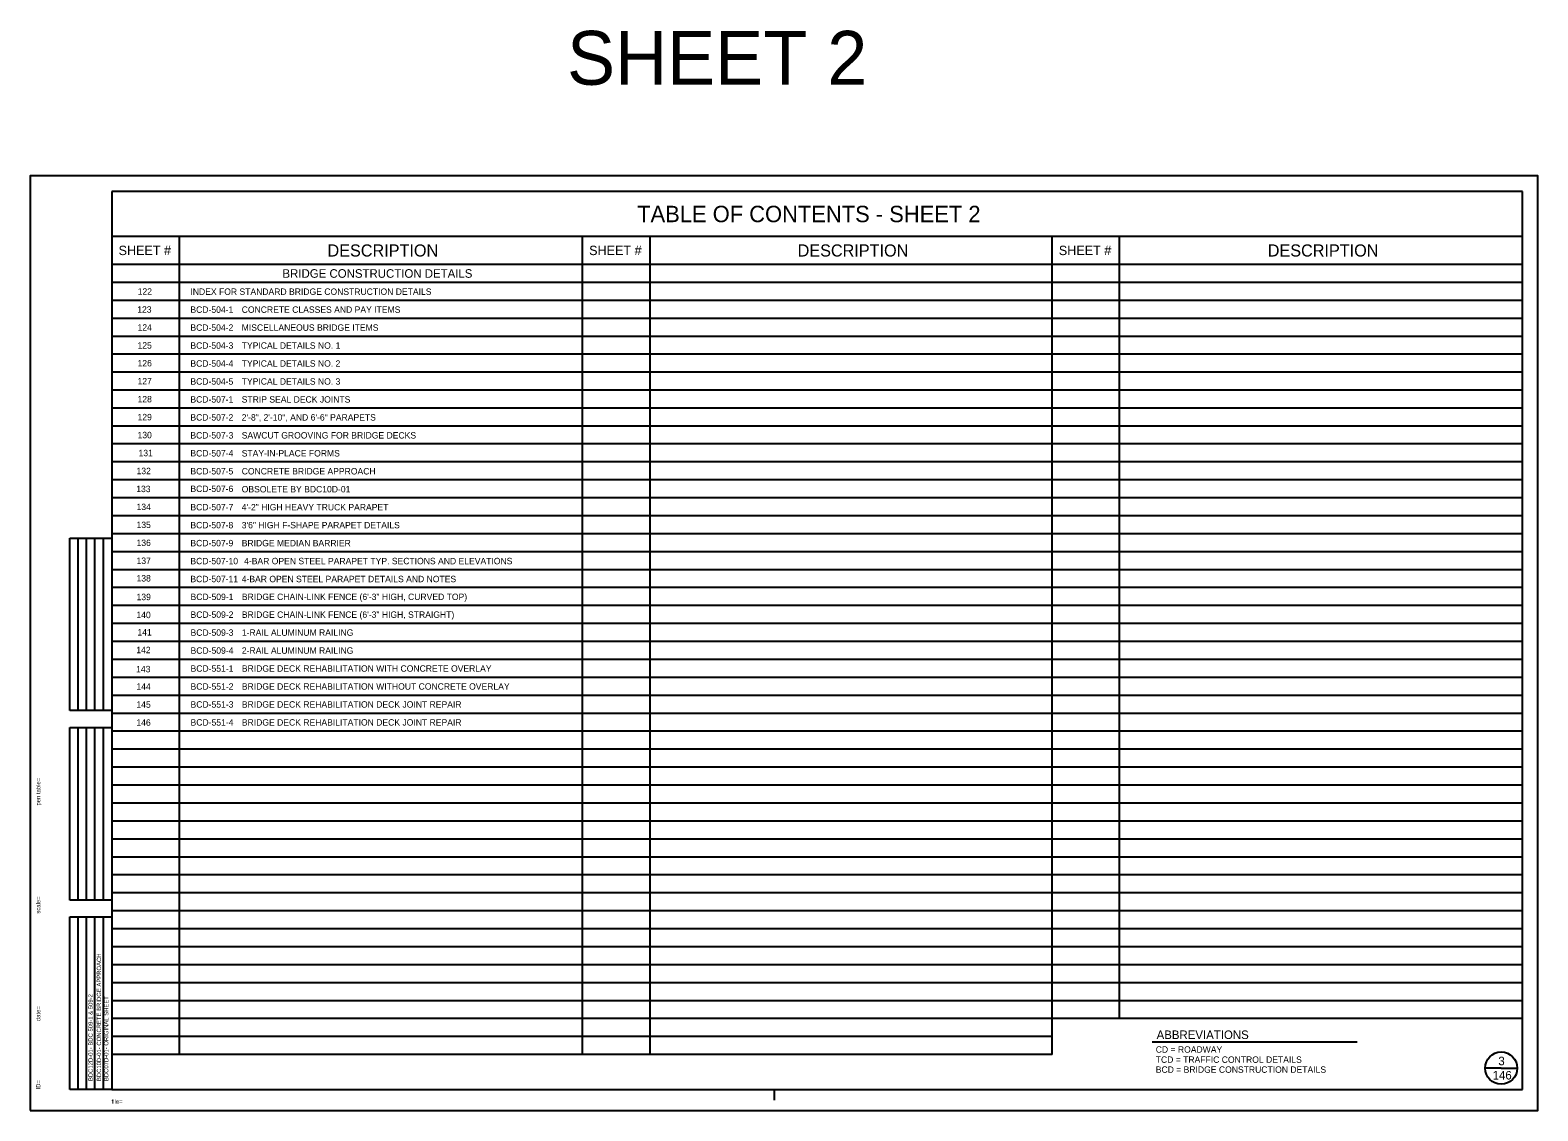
# Model space of a CAD drawing. Extents: x 499943 to 502231, y 501090 to 501849.
# Drawn here: x 501173 to 502231, y 501090 to 501849 of the extents above; entities that cross this region are included whole.
import ezdxf

# ---------------------------------------------------------------- set-up
doc = ezdxf.new("R2010")
doc.units = 0
for name, color, linetype in [('1', 7, 'Continuous'), ('39', 7, 'Continuous'), ('41', 7, 'Continuous')]:
    doc.layers.add(name, color=color, linetype=linetype)

msp = doc.modelspace()

# ---------------------------------------------------------------- linework, layer by layer
at = {"layer": '1'}
for p, q in [((502224.2, 501746.3), (501176, 501746.3)), ((501230.6, 501735.3), (501230.6, 501105.3)), ((502220.6, 501735.3), (501230.6, 501735.3)), ((502220.6, 501105.3), (502220.6, 501735.3)), ((501277.9, 501703.8), (501230.6, 501703.8)), ((501277.9, 501703.8), (501277.9, 501129.8)), ((501560.8, 501703.8), (501277.9, 501703.8)), ((501560.8, 501703.8), (501560.8, 501129.8)), ((501608.1, 501703.8), (501560.8, 501703.8)), ((501608.1, 501703.8), (501608.1, 501129.8)), ((501890.5, 501703.8), (501608.1, 501703.8)), ((501937.7, 501703.8), (501890.5, 501703.8)), ((501890.5, 501155), (501890.5, 501703.8)), ((502220.6, 501703.8), (501937.7, 501703.8)), ((501937.7, 501155), (501937.7, 501703.8)), ((502220.6, 501684.1), (501230.6, 501684.1)), ((502220.6, 501671.5), (501230.6, 501671.5)), ((502220.6, 501658.9), (501230.6, 501658.9)), ((502220.6, 501646.3), (501230.6, 501646.3)), ((502220.6, 501633.7), (501230.6, 501633.7)), ((502220.6, 501621.1), (501230.6, 501621.1)), ((502220.6, 501608.5), (501230.6, 501608.5)), ((502220.6, 501595.9), (501230.6, 501595.9)), ((502220.6, 501583.3), (501230.6, 501583.3)), ((502220.6, 501570.7), (501230.6, 501570.7)), ((502220.6, 501558.2), (501230.6, 501558.2)), ((502220.6, 501545.6), (501230.6, 501545.6)), ((502220.6, 501533), (501230.6, 501533)), ((502220.6, 501520.4), (501230.6, 501520.4)), ((502220.6, 501507.8), (501230.6, 501507.8)), ((501201.1, 501371.1), (501201.1, 501492.1)), ((501201.1, 501492.1), (501230.6, 501492.1)), ((501207, 501371.1), (501207, 501492.1)), ((501212.9, 501371.1), (501212.9, 501492.1)), ((501218.8, 501371.1), (501218.8, 501492.1)), ((501224.7, 501371.1), (501224.7, 501492.1)), ((502220.6, 501495.2), (501230.6, 501495.2)), ((502220.6, 501482.6), (501230.6, 501482.6)), ((502220.6, 501470), (501230.6, 501470)), ((502220.6, 501457.4), (501230.6, 501457.4)), ((502220.6, 501444.8), (501230.6, 501444.8)), ((502220.6, 501432.2), (501230.6, 501432.2)), ((502220.6, 501419.6), (501230.6, 501419.6)), ((502220.6, 501407), (501230.6, 501407)), ((502220.6, 501394.4), (501230.6, 501394.4)), ((502220.6, 501381.8), (501230.6, 501381.8)), ((501230.6, 501371.1), (501201.1, 501371.1)), ((502220.6, 501369.2), (501230.6, 501369.2)), ((501201.1, 501238.2), (501201.1, 501359.3)), ((501201.1, 501359.3), (501230.6, 501359.3)), ((501207, 501238.2), (501207, 501359.3)), ((501212.9, 501238.2), (501212.9, 501359.3)), ((501218.8, 501238.2), (501218.8, 501359.3)), ((501224.7, 501238.2), (501224.7, 501359.3)), ((502220.6, 501356.6), (501230.6, 501356.6)), ((502220.6, 501344), (501230.6, 501344)), ((502220.6, 501331.4), (501230.6, 501331.4)), ((502220.6, 501318.8), (501230.6, 501318.8)), ((502220.6, 501306.2), (501230.6, 501306.2)), ((502220.6, 501293.6), (501230.6, 501293.6)), ((502220.6, 501281), (501230.6, 501281)), ((502220.6, 501268.4), (501230.6, 501268.4)), ((502220.6, 501255.8), (501230.6, 501255.8)), ((501230.6, 501238.2), (501201.1, 501238.2)), ((502220.6, 501243.2), (501230.6, 501243.2)), ((501201.1, 501105.3), (501201.1, 501226.4)), ((501201.1, 501226.4), (501230.6, 501226.4)), ((501207, 501105.3), (501207, 501226.4)), ((501212.9, 501105.3), (501212.9, 501226.4)), ((501218.8, 501105.3), (501218.8, 501226.4)), ((501224.7, 501105.3), (501224.7, 501226.4)), ((502220.6, 501230.6), (501230.6, 501230.6)), ((502220.6, 501218), (501230.6, 501218)), ((502220.6, 501205.4), (501230.6, 501205.4)), ((502220.6, 501192.8), (501230.6, 501192.8)), ((502220.6, 501180.2), (501230.6, 501180.2)), ((502220.6, 501167.6), (501230.6, 501167.6)), ((501890.5, 501155), (501230.6, 501155)), ((502220.6, 501155), (501890.5, 501155)), ((501890.5, 501129.8), (501890.5, 501155)), ((501890.5, 501142.4), (501230.6, 501142.4)), ((501890.5, 501142.4), (501560.8, 501142.4)), ((501560.8, 501129.8), (501230.6, 501129.8)), ((501890.5, 501129.8), (501560.8, 501129.8)), ((502104.6, 501138.5), (501960.6, 501138.5)), ((502205.6, 501120.3), (502194.4, 501120.3)), ((502205.6, 501120.3), (502216.9, 501120.3)), ((501230.6, 501105.3), (501201.1, 501105.3)), ((501230.6, 501105.3), (502220.6, 501105.3)), ((501695.6, 501097.8), (501695.6, 501105.3)), ((502228.2, 501090.3), (501180, 501090.3))]:
    msp.add_line(p, q, dxfattribs=at)
msp.add_circle((502205.6, 501120.3), 11.3, dxfattribs=at)
at = {"layer": '41'}
msp.add_lwpolyline([(501173.3, 501090.6), (502231.3, 501090.6), (502231.3, 501746.3), (501173.3, 501746.3)], close=True, dxfattribs=at)

# ---------------------------------------------------------------- texts
at = {"layer": '1'}
for s, height, p in [('TABLE OF CONTENTS - SHEET 2', 11.5, (501599.3, 501713.8)), ('3', 6, (502203.6, 501122.3)), ('146', 6, (502199.6, 501112.3))]:
    msp.add_text(s, height=height, dxfattribs=at).set_placement(p)
for s, height, rotation, p in [('pen table=', 3, 90, (501180.5, 501304.5)), ('...................pentable..................', 0.0432, 90, (501180.5, 501328.4)), ('scale=', 3, 90, (501180.5, 501228.7)), ('......scale......', 0.0432, 90, (501180.5, 501243.4)), ('BDC10D-01- CONCRETE BRIDGE APPROACH', 3, 90, (501223.1, 501111.2)), ('date=', 3, 90, (501180.5, 501153.3)), ('.......time......', 0.0432, 90, (501180.5, 501166.4)), ('BDC12D-01- BDC 509-1 & 509-2', 3, 90, (501217.2, 501111.2)), ('BDC07D-01- ORIGINAL SHEET', 3, 90, (501228.2, 501111.2)), ('ID=', 3, 90, (501180.5, 501105.3)), ('............who............', 0.0432, 90, (501180.5, 501113.3)), ('file=', 3, 360, (501230.5, 501095.3)), ('...................bob..................', 0.0432, 360, (501240.5, 501095.3))]:
    msp.add_text(s, height=height, rotation=rotation, dxfattribs=at).set_placement(p)
at = {"layer": '39'}
for s, height, p in [('SHEET 2', 37.8, (501550.1, 501810.2)), ('SHEET #', 6.6, (501235.4, 501690.7)), ('DESCRIPTION', 8.5, (501382, 501689.7)), ('SHEET #', 6.6, (501565.6, 501690.7)), ('DESCRIPTION', 8.5, (501711.9, 501689.7)), ('SHEET #', 6.6, (501895.2, 501690.7)), ('DESCRIPTION', 8.5, (502041.8, 501689.7)), ('BRIDGE CONSTRUCTION DETAILS', 6, (501350.4, 501674.8)), ('122', 4.5, (501248.8, 501662.9)), ('INDEX FOR STANDARD BRIDGE CONSTRUCTION DETAILS', 4.5, (501285.8, 501662.8)), ('123', 4.5, (501248.5, 501650.3)), ('BCD-504-1', 4.5, (501285.8, 501650.2)), ('CONCRETE CLASSES AND PAY ITEMS', 4.5, (501321.8, 501650.2)), ('124', 4.5, (501248.7, 501637.7)), ('BCD-504-2', 4.5, (501285.8, 501637.6)), ('MISCELLANEOUS BRIDGE ITEMS', 4.5, (501321.8, 501637.6)), ('125', 4.5, (501248.7, 501625.1)), ('BCD-504-3', 4.5, (501285.8, 501625)), ('TYPICAL DETAILS NO. 1', 4.5, (501321.8, 501625)), ('126', 4.5, (501248.7, 501612.6)), ('BCD-504-4', 4.5, (501285.8, 501612.4)), ('TYPICAL DETAILS NO. 2', 4.5, (501321.8, 501612.4)), ('127', 4.5, (501248.7, 501600)), ('BCD-504-5', 4.5, (501285.8, 501599.8)), ('TYPICAL DETAILS NO. 3', 4.5, (501321.8, 501599.8)), ('128', 4.5, (501248.7, 501587.4)), ('BCD-507-1', 4.5, (501285.8, 501587.2)), ('STRIP SEAL DECK JOINTS', 4.5, (501321.8, 501587.2)), ('129', 4.5, (501248.7, 501574.8)), ('BCD-507-2', 4.5, (501285.8, 501574.6)), ('2\'-8", 2\'-10", AND 6\'-6" PARAPETS', 4.5, (501321.8, 501574.6)), ('130', 4.5, (501248.7, 501562.2)), ('BCD-507-3', 4.5, (501285.8, 501562)), ('SAWCUT GROOVING FOR BRIDGE DECKS', 4.5, (501321.8, 501562)), ('131', 4.5, (501249.4, 501549.6)), ('BCD-507-4', 4.5, (501285.8, 501549.4)), ('STAY-IN-PLACE FORMS', 4.5, (501321.8, 501549.4)), ('132', 4.5, (501248, 501537)), ('BCD-507-5', 4.5, (501285.8, 501536.8)), ('CONCRETE BRIDGE APPROACH ', 4.5, (501321.8, 501536.8)), ('133', 4.5, (501247.8, 501524.4)), ('BCD-507-6', 4.5, (501285.8, 501524.5)), ('OBSOLETE BY BDC10D-01', 4.5, (501321.8, 501524.2)), ('134', 4.5, (501248, 501511.8)), ('BCD-507-7', 4.5, (501285.8, 501511.6)), ('4\'-2" HIGH HEAVY TRUCK PARAPET', 4.5, (501321.8, 501511.6)), ('135', 4.5, (501248, 501499.2)), ('BCD-507-8', 4.5, (501285.8, 501499)), ('3\'6" HIGH F-SHAPE PARAPET DETAILS', 4.5, (501321.8, 501499)), ('136', 4.5, (501248, 501486.6)), ('BCD-507-9', 4.5, (501285.8, 501486.4)), ('BRIDGE MEDIAN BARRIER', 4.5, (501321.8, 501486.4)), ('137', 4.5, (501248, 501474)), ('BCD-507-10', 4.5, (501285.8, 501473.8)), (' 4-BAR OPEN STEEL PARAPET TYP. SECTIONS AND ELEVATIONS', 4.5, (501321.8, 501473.8)), ('138', 4.5, (501248, 501461.7)), ('BCD-507-11', 4.5, (501285.8, 501461.2)), ('4-BAR OPEN STEEL PARAPET DETAILS AND NOTES', 4.5, (501321.8, 501461.2)), ('139', 4.5, (501248, 501448.6)), ('BCD-509-1', 4.5, (501285.9, 501448.7)), ('BRIDGE CHAIN-LINK FENCE (6\'-3" HIGH, CURVED TOP)', 4.5, (501321.9, 501448.7)), ('140', 4.5, (501247.9, 501436)), ('BCD-509-2', 4.5, (501285.9, 501436.2)), ('BRIDGE CHAIN-LINK FENCE (6\'-3" HIGH, STRAIGHT)', 4.5, (501321.9, 501436.2)), ('141', 4.5, (501248.6, 501423.8)), ('BCD-509-3', 4.5, (501285.9, 501423.6)), ('1-RAIL ALUMINUM RAILING', 4.5, (501321.9, 501423.6)), ('142', 4.5, (501247.8, 501411.4)), ('BCD-509-4', 4.5, (501285.9, 501411)), ('2-RAIL ALUMINUM RAILING', 4.5, (501321.9, 501411)), ('143', 4.5, (501247.7, 501398)), ('BCD-551-1', 4.5, (501285.9, 501398.4)), ('BRIDGE DECK REHABILITATION WITH CONCRETE OVERLAY', 4.5, (501321.9, 501398.4)), ('144', 4.5, (501247.9, 501385.7)), ('BCD-551-2', 4.5, (501285.9, 501385.8)), ('BRIDGE DECK REHABILITATION WITHOUT CONCRETE OVERLAY', 4.5, (501321.9, 501385.8)), ('145', 4.5, (501247.9, 501373.1)), ('BCD-551-3', 4.5, (501285.9, 501373.2)), ('BRIDGE DECK REHABILITATION DECK JOINT REPAIR', 4.5, (501321.9, 501373.2)), ('146', 4.5, (501247.9, 501360.5)), ('BCD-551-4', 4.5, (501285.9, 501360.6)), ('BRIDGE DECK REHABILITATION DECK JOINT REPAIR', 4.5, (501321.9, 501360.6)), ('ABBREVIATIONS', 6, (501963.8, 501140.7)), ('CD = ROADWAY ', 4.5, (501963.2, 501131.1)), ('TCD = TRAFFIC CONTROL DETAILS', 4.5, (501963.2, 501124)), ('BCD = BRIDGE CONSTRUCTION DETAILS', 4.5, (501963.2, 501117))]:
    msp.add_text(s, height=height, dxfattribs=at).set_placement(p)

doc.saveas('drawing.dxf')
